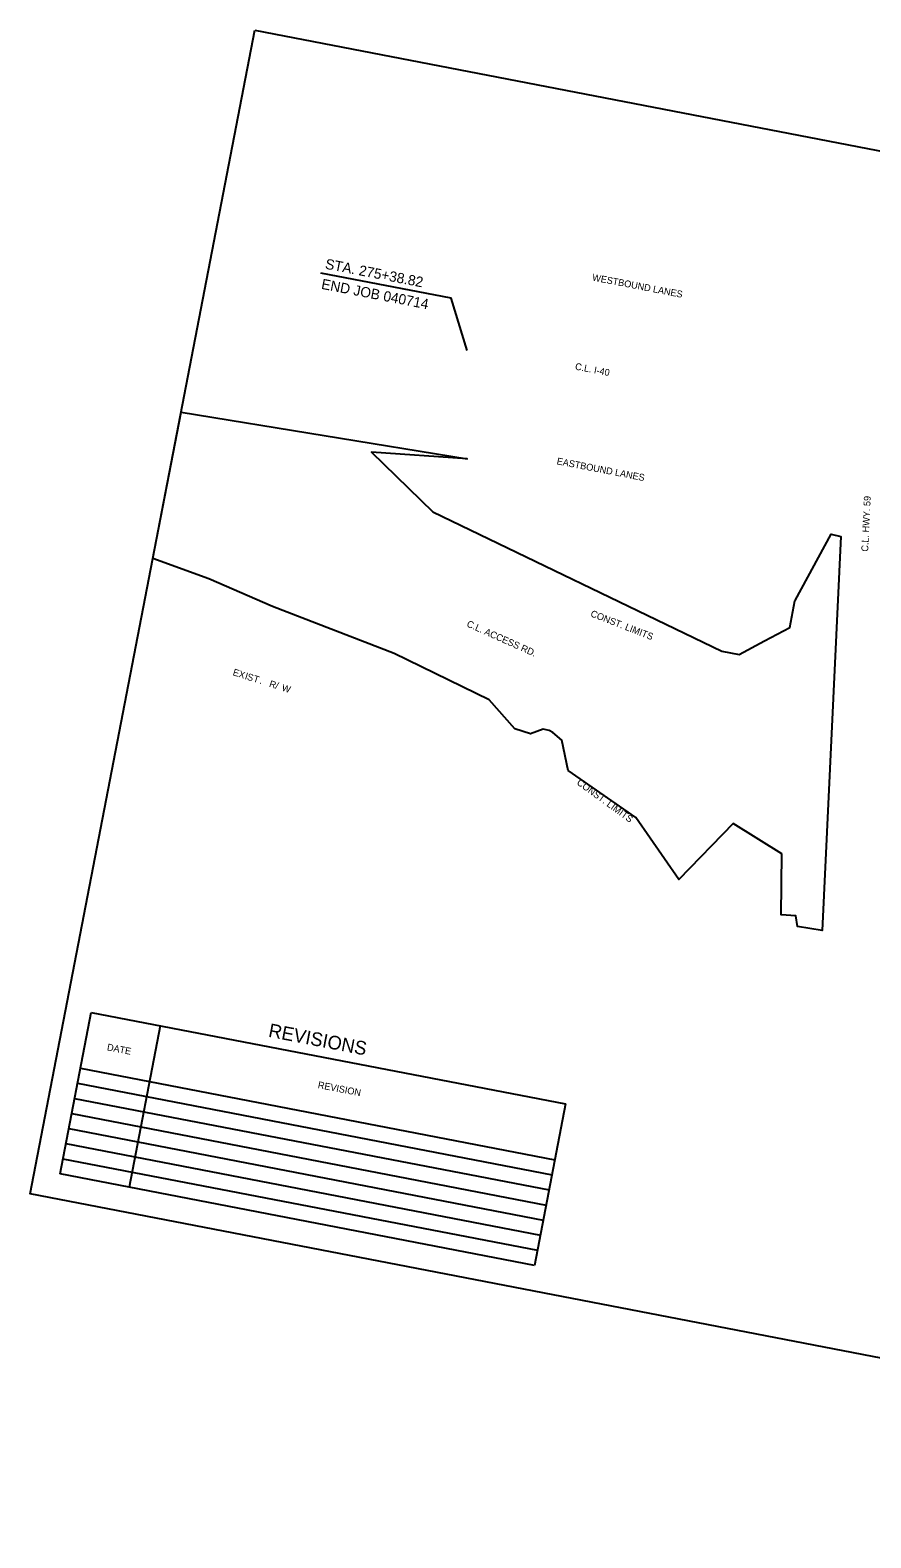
# Model space of a CAD drawing. Extents: x 607205 to 611729, y 416008 to 419873.
# Drawn here: x 609974 to 610714, y 418547 to 419873 of the extents above; entities that cross this region are included whole.
import ezdxf

# ---------------------------------------------------------------- set-up
doc = ezdxf.new("R2010")
doc.units = 0
for name, color, linetype in [('Default', 7, 'Continuous'), ('R_Draft', 7, 'Continuous'), ('TP_Mask', 7, 'Continuous'), ('X_ARROWS_LEGEND', 7, 'Continuous')]:
    doc.layers.add(name, color=color, linetype=linetype)

msp = doc.modelspace()

# ---------------------------------------------------------------- linework, layer by layer
at = {"layer": 'R_Draft'}
msp.add_lwpolyline([(610358.7, 419591.5), (610344.5, 419637.5), (610230, 419659.6)], dxfattribs=at)
at = {"layer": 'TP_Mask'}
for points in [[(610171.9, 419873.3), (611428.7, 419630.7), (611419.3, 419582), (611533.5, 419560), (611729, 419522.3), (611726, 419507.1), (611540.8, 418547.5), (609974.4, 418849.9)], [(610082.2, 419408.8), (610107.1, 419537.4), (610358.7, 419496.2), (610274.7, 419502.2), (610328.4, 419449.7), (610582.6, 419327.2), (610597.9, 419324.4), (610620.2, 419336.2), (610642.4, 419348), (610646.8, 419371.4), (610647, 419371.7), (610678.8, 419430.1), (610687.3, 419427.9), (610670.8, 419081.5), (610649.3, 419085.1), (610647.8, 419094.6), (610634.7, 419095.4), (610635.3, 419148.9), (610592.6, 419175.7), (610544.7, 419126.5), (610507.1, 419180.8), (610447.4, 419222.2), (610442, 419249), (610434.1, 419255.7), (610430.9, 419257.5), (610425.5, 419258.5), (610414.5, 419254.5), (610400.6, 419258.8), (610378, 419284.3), (610294.4, 419325.2), (610187.4, 419366.6), (610131.5, 419390.8)], [(610082.2, 419408.8), (610107.1, 419537.4), (610358.7, 419496.2), (610274.7, 419502.2), (610328.4, 419449.7), (610582.6, 419327.2), (610597.9, 419324.4), (610620.2, 419336.2), (610642.4, 419348), (610646.8, 419371.4), (610647, 419371.7), (610678.8, 419430.1), (610687.3, 419427.9), (610670.8, 419081.5), (610649.3, 419085.1), (610647.8, 419094.6), (610634.7, 419095.4), (610635.3, 419148.9), (610592.6, 419175.7), (610544.7, 419126.5), (610507.1, 419180.8), (610447.4, 419222.2), (610442, 419249), (610434.1, 419255.7), (610430.9, 419257.5), (610425.5, 419258.5), (610414.5, 419254.5), (610400.6, 419258.8), (610378, 419284.3), (610294.4, 419325.2), (610187.4, 419366.6), (610131.5, 419390.8)]]:
    msp.add_lwpolyline(points, close=True, dxfattribs=at)
at = {"layer": 'X_ARROWS_LEGEND'}
for p, q in [((610000.7, 418867.6), (610028, 419009.5)), ((610028, 419009.5), (610445.3, 418929)), ((610088.7, 418997.8), (610061.3, 418855.9)), ((610018.6, 418960.4), (610435.9, 418879.9)), ((610016, 418947.2), (610433.3, 418866.6)), ((610013.5, 418933.9), (610430.7, 418853.4)), ((610445.3, 418929), (610418, 418787.1)), ((610010.9, 418920.7), (610428.2, 418840.1)), ((610010.9, 418920.7), (610428.2, 418840.1)), ((610008.3, 418907.4), (610425.6, 418826.9)), ((610005.8, 418894.2), (610423.1, 418813.6)), ((610003.2, 418880.9), (610420.5, 418800.4)), ((610418, 418787.1), (610000.7, 418867.6))]:
    msp.add_line(p, q, dxfattribs=at)

# ---------------------------------------------------------------- texts
at = {"layer": 'Default'}
for s, rotation, p in [('C.L. HWY. 59', 87.2385, (610711.3, 419414.6)), ('C.L. ACCESS RD.', 335.8864, (610357.7, 419349.1))]:
    msp.add_text(s, height=6, rotation=rotation, dxfattribs=at).set_placement(p)
at = {"layer": 'R_Draft'}
for s, height, rotation, p in [('STA. 275+38.82', 9, 349.0919, (610233.3, 419663.6)), ('WESTBOUND LANES', 6, 349.0745, (610468.3, 419653.2)), ('END JOB 040714', 9, 349.0745, (610229.9, 419645.9)), ('C.L. I-40', 6, 349.0745, (610453.2, 419574.9)), ('EASTBOUND LANES', 6, 349.0745, (610437.1, 419491.6)), ('CONST. LIMITS', 6, 338.6841, (610466.6, 419358)), ('E', 6, 342.3857, (610152.1, 419306.2)), ('X', 6, 342.3857, (610157.2, 419304.6)), ('I', 6, 342.3857, (610162.7, 419302.8)), ('S', 6, 342.3857, (610164.6, 419302.2)), ('T', 6, 342.3857, (610170, 419300.5)), ('.', 6, 342.3857, (610175.6, 419298.8)), ('R', 6, 342.3857, (610184.1, 419296)), ('/', 6, 342.3857, (610189.5, 419294.3)), ('W', 6, 342.3857, (610195.1, 419292.6)), ('CONST. LIMITS', 6, 323.9795, (610454.5, 419210.5))]:
    msp.add_text(s, height=height, rotation=rotation, dxfattribs=at).set_placement(p)
at = {"layer": 'X_ARROWS_LEGEND'}
for s, height, p in [('REVISIONS', 12, (610183.3, 418988.2)), ('DATE', 6, (610041.6, 418976.3)), ('REVISION', 6, (610227, 418943.1))]:
    msp.add_text(s, height=height, rotation=349.0745, dxfattribs=at).set_placement(p)

doc.saveas('drawing.dxf')
